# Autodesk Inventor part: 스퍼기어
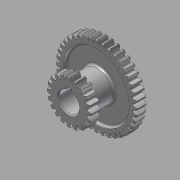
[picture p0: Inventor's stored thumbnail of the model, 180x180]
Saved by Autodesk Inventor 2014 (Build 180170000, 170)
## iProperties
Created: 2015-09
Part Number: 스퍼기어
Material: 강철, 연강
Document SubType Name: Modeling
Designer: mduedu
Density: 7.86 g/cm^3
Appearance: 강철
Mass: 345.723 g
Surface Area: 225.641 cm^2
Volume: 43.9851 cm^3
Author: mduedu
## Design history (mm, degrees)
sketch "스케치1"
  geometry: C1 r 38 at (0, 0); C2 r 40 at (0, 0); C3 r 35.5 at (0, 0); 1 further point
  constraints: 3 centre point, 3 coincident
  dimensions: "d0" = 76 diameter of C1; "d2" = 2 radial gap between concentric circles of C2 C1; "d3" = 71 diameter of C3 (computed from d0)
extrude "돌출1" new body sketch "스케치1" stored distance "d4" = 10; taper "d5" = 0 deg
sketch "스케치2"
  geometry: L1 (0, 35.5)-(0, -35.5); L2 (0, 0)-(40, 0); L3 (0, 0.57)-(39.996, 0.57); L4 (0, 1.57)-(39.969, 1.57); L5 (0, 2.07)-(39.946, 2.07); A1 r 35.5 centre (0, 0) between (0, 35.5) and (0, -35.5) reference; A2 r 40 centre (0, 0) between (40, 0) and (39.946, 2.07) reference; A3 r 9.234 centre (34.93, -7.149) between (39.996, 0.57) and (35.44, 2.07); A4 r 9.234 centre (34.93, 7.149) between (35.44, -2.07) and (39.996, -0.57); A5 r 40 centre (0, 0) between (39.996, -0.57) and (39.996, 0.57); A6 r 35.5 centre (0, 0) between (35.44, -2.07) and (35.44, 2.07); 4 further points
  constraints: 16 point on circle, 10 end point, 6 point on line, 4 centre point, 3 coincident, 3 parallel, 3 symmetric about line, 2 midpoint, 1 perpendicular, 1 vertical, 3 other
  dimensions: "d6" = 0.5 distance between parallel lines of L4 L5; "d8" = 1 distance between parallel lines of L3 L4; "d9" = 1.57 distance between parallel lines of L2 L4
extrude "돌출2" join sketch "스케치2" distance "d10" = 5; taper "d12" = 0 deg; dims "d11" = 5, "d13" = 0
fillet "모깎기1" dims "d17" = 0.5
chamfer "모따기1" distance "d21" = 1; stored, may be unused: second distance "d22" = 2, angle "d23" = 45 deg
sketch "스케치3"
  geometry: C1 r 32.5 at (0, 0); C2 r 15 at (0, 0); 1 further point
  constraints: 2 centre point, 2 coincident
  dimensions: "d27" = 65 diameter of C1; "d28" = 30 diameter of C2
extrude "돌출3" cut sketch "스케치3" distance "d29" = 3; taper "d30" = 0 deg
fillet "모깎기2" dims "d31" = 2
node "작업 평면2"
  node "작업 평면1"
sketch "스케치4"
  geometry: C1 r 15 at (0, 0) reference; 1 further point
extrude "돌출4" join sketch "스케치4" stored distance "d34" = 3; taper "d35" = 0 deg
sketch "스케치5"
  geometry: C1 r 17.5 at (0, 0); C2 r 20 at (0, 0); C3 r 22 at (0, 0); 1 further point
  constraints: 3 centre point, 3 coincident
  dimensions: "d36" = 40 diameter of C2; "d38" = 2 radial gap between concentric circles of C2 C3; "d39" = 35 diameter of C1 (= d36 - 2.5 x d38)
extrude "돌출6" join sketch "스케치5" distance "d46" = 10; taper "d47" = 0 deg
sketch "스케치6"
  geometry: L1 (0, 0)-(0, 22); L2 (-17.5, 0)-(17.5, 0); L3 (-0.57, 0)-(-0.57, 21.993); L4 (-1.57, 0)-(-1.57, 21.944); L5 (-2.07, 0)-(-2.07, 21.902); A1 r 22 centre (0, 0) between (0, 22) and (-0.57, 21.993) reference; A2 r 17.5 centre (0, 0) between (-17.5, 0) and (17.5, 0) reference; A3 r 9.431 centre (7.348, 16.868) between (-0.57, 21.993) and (-2.07, 17.377); A4 r 9.431 centre (-7.348, 16.868) between (2.07, 17.377) and (0.57, 21.993); A5 r 17.5 centre (0, 0) between (2.07, 17.377) and (-2.07, 17.377); A6 r 22 centre (0, 0) between (0.57, 21.993) and (-0.57, 21.993); 4 further points
  constraints: 16 point on circle, 10 end point, 5 point on line, 4 centre point, 3 coincident, 3 symmetric about line, 2 parallel, 2 perpendicular, 1 midpoint, 1 vertical, 3 other
  dimensions: "d40" = 0.5 distance between parallel lines of L4 L5; "d42" = 1 distance between parallel lines of L3 L4; "d43" = 1.57 distance between parallel lines of L1 L4
extrude "돌출5" join sketch "스케치6" distance "d44" = 10; taper "d45" = 0 deg
fillet "모깎기3" dims "d48" = 0.5
chamfer "모따기2" distance "d49" = 1; stored, may be unused: second distance "d50" = 2, angle "d51" = 45 deg
sketch "스케치7"
  geometry: C1 r 10 at (0, 0); 1 further point
  constraints: 1 centre point, 1 coincident
  dimensions: "d55" = 20 diameter of C1
extrude "돌출7" cut sketch "스케치7" stored distance "d56" = 10; taper "d57" = 0 deg
sketch "스케치8"
  geometry: L1 (-9.539, -3)-(-12.8, -3); L2 (-12.8, -3)-(-12.8, 3); L3 (-12.8, 3)-(-9.539, 3); L4 (-9.539, 3)-(-9.539, -3); A1 r 10 centre (0, 0) between (-9.539, -3) and (-9.539, 3) reference; 2 further points
  constraints: 8 end point, 3 point on circle, 2 parallel, 1 horizontal, 1 horizontal alignment, 1 perpendicular
  dimensions: "d58" = 6 distance of L1.end L2.end; "d60" = 22.8 distance from line of point (10, 0) L2
extrude "돌출8" cut sketch "스케치8" stored distance "d61" = 10; taper "d62" = 0 deg
chamfer "모따기3" distance "d63" = 1; stored, may be unused: second distance "d64" = 2, angle "d65" = 45 deg
fillet "모깎기4" dims "d66" = 2
node "솔리드1"
pattern_circular "원형 패턴3" dims "d25" = 360 deg
mirror "대칭1"
pattern_circular "원형 패턴4" dims "d53" = 360 deg
other parameters: "d32" = 5, "d33" = 42
